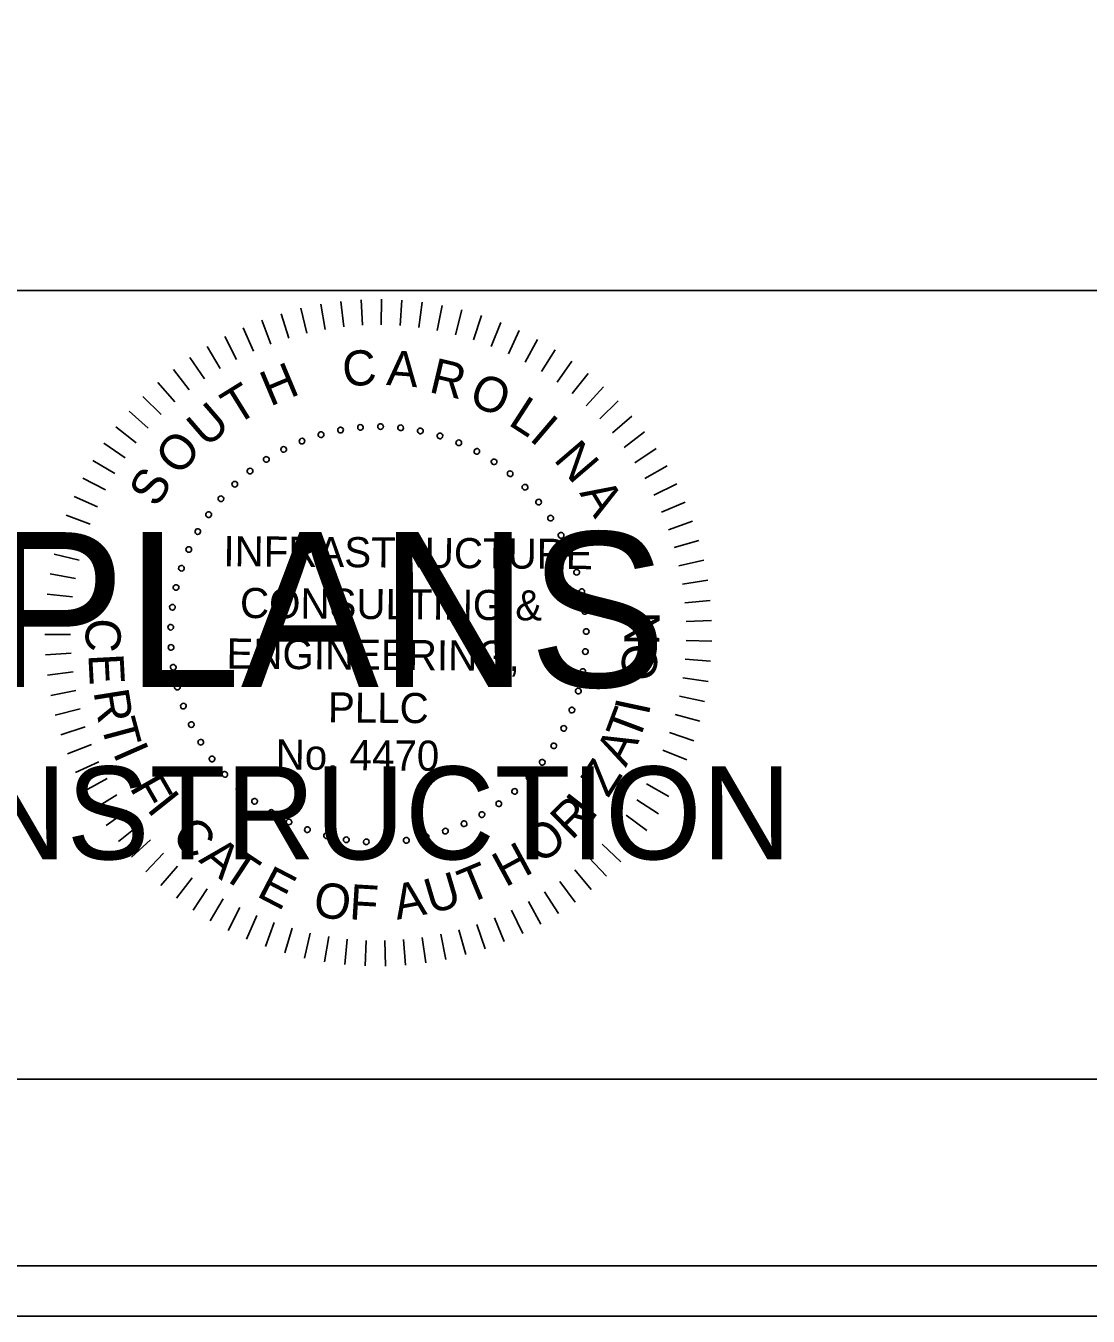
# Model space of a CAD drawing. Extents: x 967 to 1746, y 964 to 7904.
# Drawn here: x 1189.3 to 1212.88, y 5443.72 to 5472.36 of the extents above; entities that cross this region are included whole.
import ezdxf

# ---------------------------------------------------------------- set-up
doc = ezdxf.new("R2010")
doc.units = 0
for name, color, linetype in [('RD_SHT_Bndy', 7, 'Continuous'), ('RD_SHT_IplotShp', 7, 'Continuous'), ('RD_SHT_Misc1', 7, 'Continuous'), ('RD_SHT_Misc2', 7, 'Continuous'), ('RD_Sketch1', 7, 'Continuous')]:
    doc.layers.add(name, color=color, linetype=linetype)

msp = doc.modelspace()

# ---------------------------------------------------------------- linework, layer by layer
at = {"layer": 'RD_SHT_Bndy'}
for p, q in [((996.114, 5466.486), (1323.886, 5466.486)), ((1323.886, 5448.983), (996.114, 5448.983))]:
    msp.add_line(p, q, dxfattribs=at)
at = {"layer": 'RD_SHT_IplotShp'}
for points in [[(967.409, 5443.72), (1326.285, 5443.72), (1326.285, 5663.72), (967.409, 5663.72)], [(988.525, 5444.84), (1326.285, 5444.84), (1326.285, 5662.6), (988.525, 5662.6)]]:
    msp.add_lwpolyline(points, close=True, dxfattribs=at)
at = {"layer": 'RD_SHT_Misc1'}
for p, q in [((1196.292, 5466.245), (1196.357, 5465.68)), ((1196.742, 5466.282), (1196.772, 5465.714)), ((1197.194, 5466.292), (1197.189, 5465.723)), ((1197.645, 5466.274), (1197.606, 5465.706)), ((1198.094, 5466.228), (1198.02, 5465.664)), ((1194.968, 5465.971), (1195.134, 5465.427)), ((1195.403, 5466.09), (1195.536, 5465.536)), ((1195.846, 5466.181), (1195.945, 5465.62)), ((1198.54, 5466.156), (1198.432, 5465.596)), ((1198.98, 5466.056), (1198.838, 5465.504)), ((1199.414, 5465.929), (1199.238, 5465.387)), ((1194.122, 5465.656), (1194.353, 5465.136)), ((1194.54, 5465.827), (1194.739, 5465.293)), ((1199.839, 5465.777), (1199.63, 5465.246)), ((1193.715, 5465.461), (1193.978, 5464.956)), ((1200.253, 5465.598), (1200.013, 5465.082)), ((1200.656, 5465.395), (1200.385, 5464.894)), ((1193.321, 5465.241), (1193.614, 5464.752)), ((1201.047, 5465.167), (1200.745, 5464.684)), ((1192.94, 5464.997), (1193.263, 5464.528)), ((1201.422, 5464.917), (1201.092, 5464.453)), ((1192.576, 5464.731), (1192.926, 5464.282)), ((1201.781, 5464.643), (1201.424, 5464.2)), ((1192.228, 5464.443), (1192.605, 5464.016)), ((1202.124, 5464.349), (1201.739, 5463.928)), ((1191.899, 5464.134), (1192.301, 5463.731)), ((1202.447, 5464.034), (1202.038, 5463.638)), ((1191.589, 5463.805), (1192.015, 5463.428)), ((1202.751, 5463.7), (1202.318, 5463.329)), ((1191.299, 5463.459), (1191.748, 5463.108)), ((1203.034, 5463.348), (1202.579, 5463.004)), ((1191.032, 5463.095), (1191.501, 5462.772)), ((1203.294, 5462.979), (1202.82, 5462.664)), ((1190.787, 5462.716), (1191.274, 5462.422)), ((1203.532, 5462.595), (1203.04, 5462.31)), ((1190.565, 5462.323), (1191.07, 5462.059)), ((1203.746, 5462.198), (1203.237, 5461.943)), ((1190.368, 5461.916), (1190.888, 5461.684)), ((1203.936, 5461.788), (1203.412, 5461.564)), ((1190.196, 5461.499), (1190.729, 5461.299)), ((1204.1, 5461.367), (1203.563, 5461.176)), ((1190.05, 5461.072), (1190.594, 5460.905)), ((1204.238, 5460.937), (1203.691, 5460.779)), ((1189.93, 5460.636), (1190.484, 5460.503)), ((1204.349, 5460.5), (1203.794, 5460.375)), ((1189.837, 5460.195), (1190.398, 5460.095)), ((1204.434, 5460.056), (1203.872, 5459.966)), ((1189.771, 5459.748), (1190.337, 5459.683)), ((1204.491, 5459.608), (1203.925, 5459.552)), ((1189.732, 5459.298), (1190.301, 5459.267)), ((1204.522, 5459.158), (1203.953, 5459.137)), ((1189.721, 5458.847), (1190.29, 5458.851)), ((1204.524, 5458.706), (1203.955, 5458.72)), ((1189.737, 5458.396), (1190.306, 5458.434)), ((1204.499, 5458.256), (1203.932, 5458.304)), ((1189.781, 5457.946), (1190.346, 5458.019)), ((1204.447, 5457.807), (1203.884, 5457.89)), ((1189.852, 5457.5), (1190.412, 5457.608)), ((1204.367, 5457.363), (1203.81, 5457.479)), ((1189.951, 5457.06), (1190.502, 5457.201)), ((1204.261, 5456.924), (1203.712, 5457.074)), ((1190.076, 5456.626), (1190.617, 5456.8)), ((1204.128, 5456.492), (1203.589, 5456.676)), ((1190.227, 5456.2), (1190.757, 5456.408)), ((1203.969, 5456.07), (1203.442, 5456.286)), ((1190.403, 5455.785), (1190.92, 5456.024)), ((1203.784, 5455.658), (1203.271, 5455.906)), ((1190.605, 5455.381), (1191.106, 5455.651)), ((1203.574, 5455.258), (1203.078, 5455.537)), ((1190.831, 5454.99), (1191.315, 5455.291)), ((1203.341, 5454.871), (1202.862, 5455.18)), ((1191.081, 5454.614), (1191.545, 5454.943)), ((1203.085, 5454.5), (1202.626, 5454.837)), ((1191.353, 5454.253), (1191.796, 5454.61)), ((1202.806, 5454.145), (1202.368, 5454.509)), ((1191.646, 5453.91), (1192.067, 5454.293)), ((1202.506, 5453.807), (1202.092, 5454.197)), ((1191.96, 5453.585), (1192.356, 5453.994)), ((1202.186, 5453.488), (1201.796, 5453.903)), ((1192.293, 5453.28), (1192.664, 5453.712)), ((1201.847, 5453.19), (1201.484, 5453.628)), ((1192.644, 5452.996), (1192.988, 5453.45)), ((1201.491, 5452.912), (1201.155, 5453.372)), ((1193.011, 5452.734), (1193.327, 5453.208)), ((1201.119, 5452.657), (1200.811, 5453.136)), ((1193.394, 5452.495), (1193.68, 5452.987)), ((1193.791, 5452.279), (1194.047, 5452.788)), ((1200.331, 5452.217), (1200.083, 5452.73)), ((1200.731, 5452.425), (1200.453, 5452.922)), ((1194.2, 5452.088), (1194.424, 5452.612)), ((1194.62, 5451.923), (1194.812, 5452.459)), ((1199.918, 5452.034), (1199.702, 5452.561)), ((1195.05, 5451.783), (1195.208, 5452.33)), ((1195.487, 5451.67), (1195.612, 5452.225)), ((1198.624, 5451.64), (1198.508, 5452.198)), ((1199.063, 5451.745), (1198.913, 5452.295)), ((1199.495, 5451.877), (1199.312, 5452.416)), ((1195.93, 5451.584), (1196.021, 5452.146)), ((1196.377, 5451.524), (1196.434, 5452.091)), ((1196.828, 5451.493), (1196.85, 5452.062)), ((1197.279, 5451.488), (1197.267, 5452.058)), ((1197.73, 5451.512), (1197.683, 5452.079)), ((1198.179, 5451.562), (1198.097, 5452.126))]:
    msp.add_line(p, q, dxfattribs=at)
for centre, start, end in [((1195.851, 5463.285), 16.1422, 196.1422), ((1196.285, 5463.388), 10.6038, 190.6038), ((1196.285, 5463.388), 190.6038, 10.6038), ((1196.727, 5463.447), 5.0653, 185.0653), ((1196.727, 5463.447), 185.0653, 5.0653), ((1197.172, 5463.464), 359.5268, 179.5268), ((1197.172, 5463.464), 179.5268, 359.5268), ((1197.617, 5463.438), 173.9884, 353.9884), ((1197.617, 5463.438), 353.9884, 173.9884), ((1198.057, 5463.369), 168.4499, 348.4499), ((1198.057, 5463.369), 348.4499, 168.4499), ((1198.489, 5463.258), 342.9114, 162.9114), ((1195.429, 5463.142), 21.6807, 201.6807), ((1195.429, 5463.142), 201.6807, 21.6807), ((1195.851, 5463.285), 196.1422, 16.1422), ((1198.489, 5463.258), 162.9114, 342.9114), ((1198.908, 5463.106), 157.373, 337.373), ((1198.908, 5463.106), 337.373, 157.373), ((1194.637, 5462.736), 32.7576, 212.7576), ((1194.637, 5462.736), 212.7576, 32.7576), ((1195.023, 5462.958), 27.2191, 207.2191), ((1195.023, 5462.958), 207.2191, 27.2191), ((1199.31, 5462.914), 151.8345, 331.8345), ((1199.31, 5462.914), 331.8345, 151.8345), ((1194.274, 5462.478), 38.2961, 218.2961), ((1194.274, 5462.478), 218.2961, 38.2961), ((1199.692, 5462.684), 146.2961, 326.2961), ((1199.692, 5462.684), 326.2961, 146.2961), ((1200.05, 5462.419), 320.7576, 140.7576), ((1193.937, 5462.186), 43.8345, 223.8345), ((1193.937, 5462.186), 223.8345, 43.8345), ((1200.05, 5462.419), 140.7576, 320.7576), ((1200.38, 5462.12), 315.2191, 135.2191), ((1193.63, 5461.862), 49.373, 229.373), ((1193.63, 5461.862), 229.373, 49.373), ((1200.38, 5462.12), 135.2191, 315.2191), ((1200.68, 5461.79), 129.6807, 309.6807), ((1200.68, 5461.79), 309.6807, 129.6807), ((1193.356, 5461.511), 54.9114, 234.9114), ((1193.356, 5461.511), 234.9114, 54.9114), ((1200.947, 5461.433), 124.1422, 304.1422), ((1200.947, 5461.433), 304.1422, 124.1422), ((1193.117, 5461.135), 60.4499, 240.4499), ((1193.117, 5461.135), 240.4499, 60.4499), ((1201.179, 5461.052), 118.6038, 298.6038), ((1201.179, 5461.052), 298.6038, 118.6038), ((1192.915, 5460.737), 65.9884, 245.9884), ((1192.915, 5460.737), 245.9884, 65.9884), ((1201.372, 5460.651), 113.0653, 293.0653), ((1201.372, 5460.651), 293.0653, 113.0653), ((1192.753, 5460.322), 71.5268, 251.5268), ((1192.753, 5460.322), 251.5268, 71.5268), ((1201.526, 5460.233), 107.5268, 287.5268), ((1201.526, 5460.233), 287.5268, 107.5268), ((1192.632, 5459.894), 77.0653, 257.0653), ((1192.632, 5459.894), 257.0653, 77.0653), ((1201.638, 5459.801), 101.9884, 281.9884), ((1201.638, 5459.801), 281.9884, 101.9884), ((1192.552, 5459.455), 82.6038, 262.6038), ((1192.552, 5459.455), 262.6038, 82.6038), ((1201.709, 5459.361), 96.4499, 276.4499), ((1201.709, 5459.361), 276.4499, 96.4499), ((1192.515, 5459.011), 88.1422, 268.1422), ((1192.515, 5459.011), 268.1422, 88.1422), ((1201.737, 5458.917), 90.9114, 270.9114), ((1201.737, 5458.917), 270.9114, 90.9114), ((1192.522, 5458.565), 93.6807, 273.6807), ((1192.522, 5458.565), 273.6807, 93.6807), ((1201.721, 5458.471), 85.373, 265.373), ((1201.721, 5458.471), 265.373, 85.373), ((1192.571, 5458.122), 99.2191, 279.2191), ((1192.571, 5458.122), 279.2191, 99.2191), ((1201.663, 5458.029), 79.8345, 259.8345), ((1201.663, 5458.029), 259.8345, 79.8345), ((1192.662, 5457.686), 104.7576, 284.7576), ((1192.662, 5457.686), 284.7576, 104.7576), ((1201.563, 5457.595), 74.2961, 254.2961), ((1201.563, 5457.595), 254.2961, 74.2961), ((1192.796, 5457.261), 110.2961, 290.2961), ((1192.796, 5457.261), 290.2961, 110.2961), ((1201.42, 5457.173), 68.7576, 248.7576), ((1201.42, 5457.173), 248.7576, 68.7576), ((1192.97, 5456.851), 115.8345, 295.8345), ((1192.97, 5456.851), 295.8345, 115.8345), ((1201.238, 5456.766), 63.2191, 243.2191), ((1201.238, 5456.766), 243.2191, 63.2191), ((1193.182, 5456.459), 121.373, 301.373), ((1193.182, 5456.459), 301.373, 121.373), ((1201.018, 5456.379), 57.6807, 237.6807), ((1201.018, 5456.379), 237.6807, 57.6807), ((1193.432, 5456.09), 126.9114, 306.9114), ((1193.432, 5456.09), 306.9114, 126.9114), ((1200.761, 5456.014), 52.1422, 232.1422), ((1200.761, 5456.014), 232.1422, 52.1422), ((1193.715, 5455.746), 132.4499, 312.4499), ((1193.715, 5455.746), 312.4499, 132.4499), ((1200.47, 5455.677), 46.6038, 226.6038), ((1200.47, 5455.677), 226.6038, 46.6038), ((1194.031, 5455.431), 137.9884, 317.9884), ((1194.031, 5455.431), 317.9884, 137.9884), ((1200.148, 5455.369), 41.0653, 221.0653), ((1200.148, 5455.369), 221.0653, 41.0653), ((1194.376, 5455.149), 143.5268, 323.5268), ((1194.376, 5455.149), 323.5268, 143.5268), ((1199.798, 5455.093), 35.5268, 215.5268), ((1199.798, 5455.093), 215.5268, 35.5268), ((1194.746, 5454.901), 149.0653, 329.0653), ((1194.746, 5454.901), 329.0653, 149.0653), ((1195.139, 5454.69), 334.6038, 154.6038), ((1199.422, 5454.853), 29.9884, 209.9884), ((1199.422, 5454.853), 209.9884, 29.9884), ((1195.139, 5454.69), 154.6038, 334.6038), ((1195.55, 5454.517), 160.1422, 340.1422), ((1195.55, 5454.517), 340.1422, 160.1422), ((1195.975, 5454.386), 345.6807, 165.6807), ((1198.611, 5454.486), 18.9114, 198.9114), ((1198.611, 5454.486), 198.9114, 18.9114), ((1199.026, 5454.65), 24.4499, 204.4499), ((1199.026, 5454.65), 204.4499, 24.4499), ((1195.975, 5454.386), 165.6807, 345.6807), ((1196.412, 5454.295), 171.2191, 351.2191), ((1196.412, 5454.295), 351.2191, 171.2191), ((1196.855, 5454.248), 356.7576, 176.7576), ((1196.855, 5454.248), 176.7576, 356.7576), ((1197.301, 5454.243), 2.2961, 182.2961), ((1197.301, 5454.243), 182.2961, 2.2961), ((1197.745, 5454.282), 7.8345, 187.8345), ((1197.745, 5454.282), 187.8345, 7.8345), ((1198.183, 5454.363), 13.373, 193.373), ((1198.183, 5454.363), 193.373, 13.373)]:
    msp.add_arc(centre, 0.0627, start, end, dxfattribs=at)
at = {"layer": 'RD_Sketch1'}
msp.add_lwpolyline([(967.409, 5443.72), (1326.285, 5443.72), (1326.285, 5663.72), (967.409, 5663.72)], close=True, dxfattribs=at)

# ---------------------------------------------------------------- texts
at = {"layer": 'RD_SHT_Misc1'}
for s, height, rotation, p in [('C', 0.78, 4.7281, (1196.355, 5464.346)), ('A', 0.78, 355.6981, (1197.29, 5464.39)), ('H', 0.78, 22.7882, (1194.72, 5463.904)), ('R', 0.78, 346.6681, (1198.222, 5464.238)), ('O', 0.78, 337.638, (1199.096, 5463.972)), ('T', 0.78, 31.8182, (1193.961, 5463.478)), ('U', 0.78, 40.8482, (1193.306, 5462.976)), ('L', 0.78, 327.108, (1199.981, 5463.52)), ('I', 0.78, 319.578, (1200.451, 5463.182)), ('O', 0.78, 49.8782, (1192.707, 5462.341)), ('N', 0.78, 310.548, (1200.994, 5462.728)), ('S', 0.78, 58.9083, (1192.211, 5461.642)), ('A', 0.78, 301.5179, (1201.576, 5461.991)), ('INFRASTRUCTURE', 0.66873, 359.5268, (1193.682, 5460.367)), ('CONSULTING &', 0.66873, 359.5268, (1194.051, 5459.217)), ('C', 0.78, 267.025, (1190.646, 5459.227)), ('N', 0.78, 89.2085, (1203.359, 5458.604)), ('ENGINEERING,', 0.66873, 359.5268, (1193.751, 5458.095)), ('O', 0.78, 83.2085, (1203.26, 5457.786)), ('E', 0.78, 273.025, (1190.685, 5458.408)), ('R', 0.78, 279.025, (1190.799, 5457.583)), ('PLLC', 0.6687, 359.5268, (1196.002, 5456.9)), ('I', 0.78, 77.9093, (1203.121, 5457.032)), ('T', 0.78, 285.025, (1190.955, 5456.878)), ('T', 0.78, 69.3954, (1202.891, 5456.428)), ('I', 0.78, 293.7713, (1191.221, 5456.225)), ('No. 4470', 0.6687, 359.5268, (1194.843, 5455.855)), ('A', 0.78, 63.3954, (1202.616, 5455.888)), ('Z', 0.78, 57.3954, (1202.224, 5455.206)), ('F', 0.78, 299.7713, (1191.589, 5455.455)), ('I', 0.78, 308.5268, (1191.965, 5454.973)), ('I', 0.78, 52.3339, (1201.856, 5454.69)), ('R', 0.78, 44.5268, (1201.415, 5454.267)), ('C', 0.78, 314.5268, (1192.496, 5454.346)), ('O', 0.78, 38.5268, (1200.73, 5453.731)), ('A', 0.78, 320.5268, (1193.115, 5453.822)), ('H', 0.78, 28.5268, (1199.942, 5453.23)), ('T', 0.78, 326.5268, (1193.602, 5453.478)), ('E', 0.78, 332.5268, (1194.394, 5453.051)), ('T', 0.78, 22.5268, (1199.108, 5452.856)), ('O', 0.78, 350.5268, (1195.647, 5452.614)), ('F', 0.78, 356.5268, (1196.465, 5452.532)), ('A', 0.78, 10.5268, (1197.537, 5452.517)), ('U', 0.78, 16.5268, (1198.288, 5452.638))]:
    msp.add_text(s, height=height, rotation=rotation, dxfattribs=at).set_placement(p)
at = {"layer": 'RD_SHT_Misc2'}
for s, height, p in [('FINAL PLANS', 3.4375, (1174.145, 5457.685)), ('NOT FOR CONSTRUCTION', 2.0625, (1170.901, 5453.86))]:
    msp.add_text(s, height=height, dxfattribs=at).set_placement(p)

doc.saveas('drawing.dxf')
